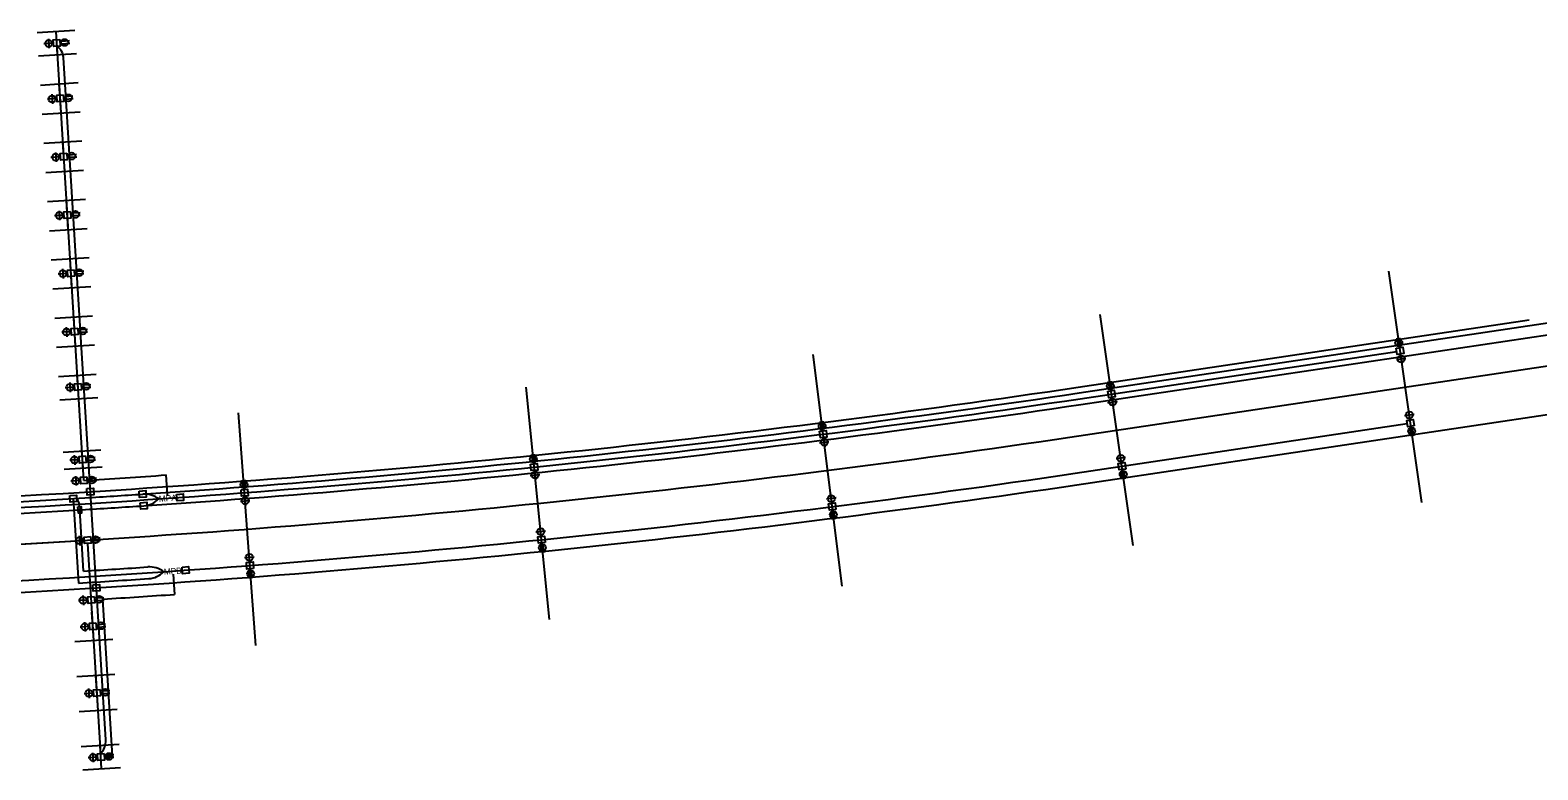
# Model space of a CAD drawing. Extents: x 927222 to 928611, y 636651 to 637029.
# Drawn here: x 927460.9 to 927719.3, y 636651.4 to 636778.1 of the extents above; entities that cross this region are included whole.
import ezdxf

# ---------------------------------------------------------------- set-up
doc = ezdxf.new("R2010")
doc.units = 0
for name, color, linetype in [('ActivePointCell_dp', 7, 'Continuous'), ('Miscellaneous2', 7, 'Continuous'), ('NonPlottingEle_dp', 7, 'Continuous'), ('PoleLight', 7, 'Continuous'), ('TextLabel', 7, 'Continuous')]:
    doc.layers.add(name, color=color, linetype=linetype)

msp = doc.modelspace()

# ---------------------------------------------------------------- linework, layer by layer
at = {"layer": 'ActivePointCell_dp'}
for p, q in [((927462.66, 636768.7), (927469.15, 636769.11)), ((927463.28, 636758.72), (927469.77, 636759.13)), ((927463.9, 636748.74), (927470.39, 636749.15)), ((927464.52, 636738.76), (927471.01, 636739.16)), ((927465.14, 636728.78), (927471.62, 636729.18)), ((927465.76, 636718.8), (927472.24, 636719.2)), ((927466.56, 636705.83), (927473.05, 636706.23)), ((927468.57, 636673.39), (927475.06, 636673.79)), ((927469.31, 636661.41), (927475.8, 636661.81))]:
    msp.add_line(p, q, dxfattribs=at)
at = {"layer": 'Miscellaneous2'}
for p, q in [((927462.11, 636777.69), (927468.59, 636778.09)), ((927465.6, 636773.9), (927465.35, 636777.89)), ((927462.35, 636773.7), (927468.84, 636774.1)), ((927466.22, 636763.92), (927465.91, 636768.91)), ((927462.97, 636763.71), (927469.46, 636764.12)), ((927466.83, 636753.93), (927466.52, 636758.92)), ((927463.59, 636753.73), (927470.08, 636754.14)), ((927467.45, 636743.95), (927467.14, 636748.94)), ((927464.21, 636743.75), (927470.7, 636744.15)), ((927468.07, 636733.97), (927467.76, 636738.96)), ((927699.41, 636697.21), (927693.74, 636736.81)), ((927464.83, 636733.77), (927471.31, 636734.17)), ((927468.69, 636723.99), (927468.38, 636728.98)), ((927649.95, 636689.83), (927644.29, 636729.42)), ((927465.45, 636723.79), (927471.93, 636724.19)), ((927600.1, 636682.86), (927595.11, 636722.55)), ((927641.76, 636708.8), (927738.03, 636723.17)), ((927641.76, 636708.8), (927738.03, 636723.17)), ((927469.25, 636715.01), (927469, 636719)), ((927549.92, 636677.15), (927545.93, 636716.95)), ((927466, 636714.81), (927472.49, 636715.21)), ((927499.62, 636672.71), (927496.62, 636712.59)), ((927469.98, 636703.12), (927469.8, 636706.03)), ((927466.74, 636702.91), (927473.23, 636703.31)), ((927471.81, 636673.59), (927471.51, 636678.41)), ((927468.94, 636667.4), (927475.43, 636667.8)), ((927472.56, 636661.61), (927472.18, 636667.6)), ((927469.68, 636655.42), (927476.17, 636655.82)), ((927473.17, 636651.63), (927472.93, 636655.62)), ((927469.93, 636651.43), (927476.42, 636651.83))]:
    msp.add_line(p, q, dxfattribs=at)
for start, end in [(273.54621, 278.49255), (273.54621, 278.49255), (266.38424, 273.54621), (266.45613, 273.54621)]:
    msp.add_arc((927347.51, 638679.45), 1992.5, start, end, dxfattribs=at)
at = {"layer": 'NonPlottingEle_dp'}
for p, q in [((927470.11, 636700.99), (927465.35, 636777.89)), ((927473.87, 636656.54), (927466.63, 636773.42)), ((927640.69, 636715.97), (927736.96, 636730.34)), ((927640.54, 636716.96), (927717.82, 636728.49)), ((927640.98, 636713.99), (927736.27, 636728.22)), ((927640.84, 636714.98), (927695.12, 636723.08)), ((927642.68, 636702.61), (927696.93, 636710.72)), ((927642.98, 636700.64), (927723.22, 636712.62)), ((927484.47, 636698.45), (927484.23, 636701.92)), ((927468.3, 636697.88), (927469.2, 636683.41)), ((927470.08, 636685.46), (927469.43, 636695.94)), ((927473.02, 636654.19), (927470.78, 636690.2)), ((927485.41, 636684.94), (927485.65, 636681.47)), ((927475.05, 636653.75), (927473.38, 636680.66)), ((927473.61, 636653.66), (927475.05, 636653.75))]:
    msp.add_line(p, q, dxfattribs=at)
for centre, radius, start, end in [((927464.28, 636773.27), 2.36, 3.5462, 58.3962), ((927347.51, 638679.45), 1984.25, 273.54621, 278.49255), ((927347.51, 638679.45), 1985.25, 273.84896, 278.49255), ((927347.51, 638679.45), 1986.25, 273.54621, 278.49255), ((927347.51, 638679.45), 1987.25, 273.85017, 278.49255), ((927347.51, 638679.45), 1982.25, 273.54621, 273.9552), ((927347.51, 638679.45), 1998.75, 273.54621, 278.49255), ((927347.51, 638679.45), 2000.75, 273.54621, 278.49255), ((927347.51, 638679.45), 1985.25, 266.45639, 273.54621), ((927347.51, 638679.45), 1984.25, 266.70547, 273.54621), ((927467.47, 636696.59), 1.92, 357.4475, 43.494), ((927347.51, 638679.45), 1985.25, 273.54621, 273.83272), ((927480.52, 636694.62), 4.03, 52.5743, 94.4684), ((927480.11, 636700.67), 4.03, 273.834, 315.1319), ((927347.51, 638679.45), 1987.25, 266.45632, 273.54621), ((927347.51, 638679.45), 1986.25, 267.16262, 273.54621), ((927347.51, 638679.45), 1987.25, 273.54621, 273.83395), ((927347.51, 638679.45), 1997.75, 273.51753, 273.83343), ((927481.38, 636682.15), 4.03, 52.5743, 94.4992), ((927480.98, 636688.19), 4.03, 273.8347, 315.1319), ((927347.51, 638679.45), 2000.75, 266.70281, 273.54621), ((927347.51, 638679.45), 1998.75, 267.16225, 273.54621), ((927347.51, 638679.45), 1999.75, 273.48891, 273.83471), ((927347.51, 638679.45), 2002.75, 273.60343, 273.9552), ((927470.75, 636656.34), 3.12, 316.381, 3.5462)]:
    msp.add_arc(centre, radius, start, end, dxfattribs=at)
at = {"layer": 'PoleLight'}
for p, q in [((927464.91, 636775.86), (927463.27, 636775.76)), ((927464.04, 636776.63), (927464.14, 636774.99)), ((927466.03, 636775.93), (927466.26, 636775.94)), ((927467.66, 636776.25), (927466.29, 636776.17)), ((927467.69, 636775.8), (927466.32, 636775.72)), ((927465.5, 636766.38), (927463.86, 636766.27)), ((927464.63, 636767.14), (927464.73, 636765.5)), ((927466.62, 636766.45), (927466.85, 636766.46)), ((927468.25, 636766.77), (927466.88, 636766.69)), ((927468.28, 636766.32), (927466.9, 636766.24)), ((927466.12, 636756.39), (927464.48, 636756.29)), ((927465.25, 636757.16), (927465.35, 636755.52)), ((927467.24, 636756.46), (927467.47, 636756.48)), ((927468.87, 636756.79), (927467.5, 636756.71)), ((927468.89, 636756.34), (927467.52, 636756.26)), ((927465.87, 636747.18), (927465.97, 636745.54)), ((927466.74, 636746.41), (927465.1, 636746.31)), ((927467.86, 636746.48), (927468.08, 636746.5)), ((927469.49, 636746.81), (927468.11, 636746.73)), ((927469.51, 636746.36), (927468.14, 636746.28)), ((927466.48, 636737.2), (927466.59, 636735.56)), ((927470.1, 636736.83), (927468.73, 636736.74)), ((927467.36, 636736.43), (927465.71, 636736.33)), ((927468.48, 636736.5), (927468.7, 636736.52)), ((927470.13, 636736.38), (927468.76, 636736.3)), ((927467.97, 636726.45), (927466.33, 636726.35)), ((927467.1, 636727.22), (927467.2, 636725.58)), ((927469.1, 636726.52), (927469.32, 636726.54)), ((927470.72, 636726.85), (927469.35, 636726.76)), ((927470.75, 636726.4), (927469.38, 636726.31)), ((927695.13, 636725.32), (927695.33, 636723.96)), ((927695.59, 636723.73), (927695.56, 636723.95)), ((927695.58, 636725.39), (927695.78, 636724.03)), ((927695.06, 636721.69), (927696.69, 636721.92)), ((927695.76, 636722.62), (927695.99, 636720.99)), ((927468.56, 636716.97), (927466.92, 636716.87)), ((927467.69, 636717.74), (927467.79, 636716.1)), ((927469.68, 636717.04), (927469.91, 636717.05)), ((927471.31, 636717.37), (927469.94, 636717.28)), ((927471.34, 636716.92), (927469.97, 636716.83)), ((927645.68, 636717.94), (927645.88, 636716.58)), ((927646.14, 636716.35), (927646.11, 636716.57)), ((927646.13, 636718), (927646.32, 636716.64)), ((927645.61, 636714.3), (927647.24, 636714.54)), ((927646.3, 636715.23), (927646.54, 636713.61)), ((927596.33, 636711.07), (927596.5, 636709.71)), ((927596.77, 636711.13), (927596.94, 636709.76)), ((927698.1, 636712.29), (927696.47, 636712.05)), ((927697.41, 636711.36), (927697.17, 636712.98)), ((927596.75, 636709.47), (927596.73, 636709.69)), ((927596.89, 636708.35), (927597.1, 636706.72)), ((927697.59, 636708.58), (927697.39, 636709.94)), ((927697.57, 636710.24), (927697.6, 636710.02)), ((927698.03, 636708.65), (927697.83, 636710.01)), ((927596.18, 636707.43), (927597.81, 636707.64)), ((927647.95, 636703.97), (927647.71, 636705.6)), ((927469.33, 636704.54), (927467.69, 636704.43)), ((927468.46, 636705.31), (927468.56, 636703.66)), ((927470.45, 636704.61), (927470.68, 636704.62)), ((927472.08, 636704.93), (927470.71, 636704.85)), ((927472.11, 636704.48), (927470.74, 636704.4)), ((927546.86, 636705.45), (927546.99, 636704.08)), ((927547.25, 636703.83), (927547.22, 636704.06)), ((927547.31, 636705.49), (927547.44, 636704.12)), ((927648.65, 636704.9), (927647.02, 636704.67)), ((927469.55, 636700.96), (927467.91, 636700.86)), ((927468.68, 636701.73), (927468.78, 636700.09)), ((927470.68, 636701.03), (927470.9, 636701.04)), ((927472.3, 636701.36), (927470.93, 636701.27)), ((927472.33, 636700.91), (927470.96, 636700.82)), ((927497.26, 636701.06), (927497.37, 636699.69)), ((927497.71, 636701.1), (927497.82, 636699.73)), ((927546.62, 636701.81), (927548.26, 636701.98)), ((927547.36, 636702.71), (927547.52, 636701.08)), ((927648.13, 636701.2), (927647.93, 636702.56)), ((927648.12, 636702.86), (927648.15, 636702.64)), ((927648.58, 636701.27), (927648.38, 636702.63)), ((927497.61, 636699.44), (927497.59, 636699.67)), ((927497.7, 636698.32), (927497.82, 636696.68)), ((927599.03, 636697.98), (927597.4, 636697.78)), ((927598.31, 636697.06), (927598.11, 636698.69)), ((927496.94, 636697.44), (927498.58, 636697.56)), ((927598.44, 636694.29), (927598.26, 636695.65)), ((927598.45, 636695.95), (927598.48, 636695.72)), ((927598.88, 636694.35), (927598.71, 636695.71)), ((927548.49, 636691.4), (927548.33, 636693.03)), ((927470.19, 636690.73), (927468.55, 636690.63)), ((927469.32, 636691.5), (927469.42, 636689.86)), ((927471.31, 636690.8), (927471.53, 636690.81)), ((927472.94, 636691.13), (927471.56, 636691.04)), ((927472.96, 636690.68), (927471.59, 636690.59)), ((927549.23, 636692.29), (927547.59, 636692.13)), ((927548.61, 636690.28), (927548.63, 636690.05)), ((927548.99, 636688.66), (927548.86, 636690.03)), ((927499.3, 636687.86), (927497.67, 636687.74)), ((927498.55, 636686.98), (927498.42, 636688.62)), ((927548.55, 636688.62), (927548.41, 636689.99)), ((927498.53, 636684.2), (927498.43, 636685.57)), ((927498.63, 636685.86), (927498.65, 636685.63)), ((927498.98, 636684.23), (927498.88, 636685.6)), ((927470.82, 636680.5), (927469.18, 636680.4)), ((927469.95, 636681.27), (927470.05, 636679.63)), ((927471.94, 636680.57), (927472.17, 636680.58)), ((927473.57, 636680.9), (927472.2, 636680.81)), ((927473.6, 636680.45), (927472.23, 636680.36)), ((927471.1, 636675.97), (927469.46, 636675.86)), ((927470.23, 636676.73), (927470.33, 636675.09)), ((927472.23, 636676.04), (927472.45, 636676.05)), ((927473.85, 636676.36), (927472.48, 636676.28)), ((927473.88, 636675.91), (927472.51, 636675.83)), ((927471.81, 636664.57), (927470.17, 636664.47)), ((927470.94, 636665.34), (927471.04, 636663.7)), ((927472.93, 636664.64), (927473.16, 636664.65)), ((927474.56, 636664.97), (927473.19, 636664.88)), ((927474.59, 636664.52), (927473.21, 636664.43)), ((927471.62, 636654.36), (927471.72, 636652.72)), ((927475.24, 636653.99), (927473.87, 636653.9)), ((927472.49, 636653.59), (927470.85, 636653.49)), ((927473.61, 636653.66), (927473.84, 636653.68)), ((927475.27, 636653.54), (927473.89, 636653.45))]:
    msp.add_line(p, q, dxfattribs=at)
for centre in [(927464.09, 636775.81), (927466.85, 636775.98), (927464.68, 636766.32), (927467.44, 636766.5), (927465.3, 636756.34), (927468.06, 636756.52), (927465.92, 636746.36), (927468.68, 636746.53), (927466.53, 636736.38), (927469.3, 636736.55), (927467.15, 636726.4), (927469.92, 636726.57), (927695.47, 636724.54), (927695.87, 636721.8), (927467.74, 636716.92), (927470.5, 636717.09), (927646.02, 636717.16), (927646.42, 636714.42), (927596.65, 636710.28), (927697.29, 636712.17), (927597, 636707.54), (927697.69, 636709.43), (927468.51, 636704.49), (927471.27, 636704.66), (927547.16, 636704.65), (927647.83, 636704.79), (927468.73, 636700.91), (927471.5, 636701.08), (927497.55, 636700.26), (927547.44, 636701.9), (927648.24, 636702.05), (927497.76, 636697.5), (927598.21, 636697.88), (927598.56, 636695.13), (927548.41, 636692.21), (927469.37, 636690.68), (927472.13, 636690.85), (927548.69, 636689.46), (927498.49, 636687.8), (927498.69, 636685.04), (927470, 636680.45), (927472.76, 636680.62), (927470.28, 636675.91), (927473.05, 636676.09), (927470.99, 636664.52), (927473.75, 636664.69), (927471.67, 636653.54), (927474.43, 636653.71)]:
    msp.add_circle(centre, 0.597, dxfattribs=at)
at = {"layer": 'TextLabel'}
msp.add_line((927469.18, 636695.36), (927469.67, 636696.52), dxfattribs=at)
for points in [[(927466, 636776.49), (927466.07, 636775.37), (927464.95, 636775.3), (927464.88, 636776.42)], [(927466.59, 636767.01), (927466.66, 636765.88), (927465.53, 636765.81), (927465.46, 636766.94)], [(927467.21, 636757.03), (927467.28, 636755.9), (927466.15, 636755.83), (927466.08, 636756.96)], [(927467.82, 636747.05), (927467.89, 636745.92), (927466.77, 636745.85), (927466.7, 636746.98)], [(927468.44, 636737.06), (927468.51, 636735.94), (927467.39, 636735.87), (927467.32, 636736.99)], [(927469.06, 636727.08), (927469.13, 636725.96), (927468.01, 636725.89), (927467.94, 636727.01)], [(927695.04, 636723.65), (927696.15, 636723.81), (927696.31, 636722.7), (927695.2, 636722.54)], [(927469.65, 636717.6), (927469.72, 636716.48), (927468.6, 636716.41), (927468.53, 636717.53)], [(927645.58, 636716.26), (927646.7, 636716.43), (927646.86, 636715.31), (927645.75, 636715.15)], [(927698.13, 636710.33), (927697.01, 636710.16), (927696.85, 636711.27), (927697.96, 636711.44)], [(927596.2, 636709.4), (927597.31, 636709.54), (927597.45, 636708.42), (927596.34, 636708.28)], [(927470.42, 636705.17), (927470.49, 636704.04), (927469.37, 636703.97), (927469.3, 636705.1)], [(927546.69, 636703.78), (927547.81, 636703.89), (927547.92, 636702.77), (927546.8, 636702.66)], [(927648.67, 636702.94), (927647.56, 636702.78), (927647.4, 636703.89), (927648.51, 636704.05)], [(927470.64, 636701.59), (927470.71, 636700.47), (927469.59, 636700.4), (927469.52, 636701.52)], [(927467.71, 636698.4), (927468.83, 636698.47), (927468.9, 636697.35), (927467.78, 636697.28)], [(927470.64, 636699.59), (927471.76, 636699.66), (927471.83, 636698.53), (927470.71, 636698.46)], [(927479.61, 636699.17), (927480.73, 636699.24), (927480.8, 636698.11), (927479.68, 636698.04)], [(927486.01, 636698.6), (927487.13, 636698.68), (927487.21, 636697.56), (927486.09, 636697.48)], [(927497.05, 636699.4), (927498.17, 636699.49), (927498.26, 636698.36), (927497.13, 636698.28)], [(927469.11, 636696.49), (927469.67, 636696.52), (927469.74, 636695.4), (927469.18, 636695.36)], [(927479.79, 636697.17), (927480.91, 636697.24), (927480.98, 636696.12), (927479.86, 636696.05)], [(927599.01, 636696.02), (927597.9, 636695.88), (927597.76, 636696.99), (927598.87, 636697.13)], [(927471.28, 636691.36), (927471.35, 636690.24), (927470.22, 636690.17), (927470.15, 636691.29)], [(927549.17, 636690.33), (927548.05, 636690.22), (927547.93, 636691.34), (927549.05, 636691.45)], [(927486.94, 636686.14), (927488.07, 636686.22), (927488.14, 636685.09), (927487.02, 636685.02)], [(927499.19, 636685.9), (927498.07, 636685.81), (927497.99, 636686.94), (927499.11, 636687.02)], [(927471.66, 636683.12), (927472.78, 636683.19), (927472.85, 636682.07), (927471.73, 636682)], [(927471.91, 636681.13), (927471.98, 636680.01), (927470.86, 636679.94), (927470.79, 636681.06)], [(927472.19, 636676.6), (927472.26, 636675.47), (927471.14, 636675.4), (927471.07, 636676.53)], [(927472.9, 636665.2), (927472.97, 636664.08), (927471.84, 636664.01), (927471.77, 636665.13)], [(927473.58, 636654.22), (927473.65, 636653.1), (927472.52, 636653.03), (927472.45, 636654.15)]]:
    msp.add_lwpolyline(points, close=True, dxfattribs=at)

# ---------------------------------------------------------------- texts
at = {"layer": 'PoleLight'}
for s, p in [('MPA', (927483.01, 636697.3)), ('MPB', (927483.87, 636684.83))]:
    msp.add_text(s, height=1.05, rotation=3.9552, dxfattribs=at).set_placement(p)

doc.saveas('drawing.dxf')
